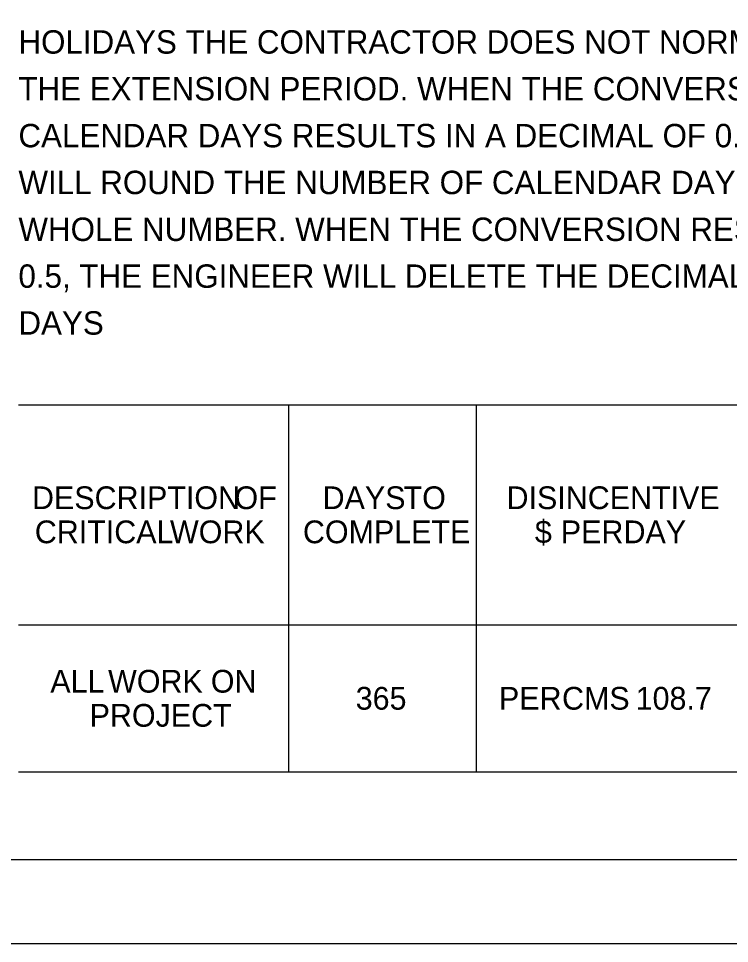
# Model space of a CAD drawing. Extents: x 0 to 84.3, y -13.4 to 22.
# Drawn here: x 24.66 to 28.91, y 0 to 5.53 of the extents above; entities that cross this region are included whole.
import ezdxf

# ---------------------------------------------------------------- set-up
doc = ezdxf.new("R2010")
doc.units = 0
for name, color, linetype in [('SH_Border', 7, 'Continuous'), ('SH_Cut_Line', 7, 'Continuous'), ('SH_Text', 7, 'Continuous')]:
    doc.layers.add(name, color=color, linetype=linetype)

msp = doc.modelspace()

# ---------------------------------------------------------------- linework, layer by layer
at = {"layer": 'SH_Border'}
msp.add_lwpolyline([(1.5, 21.5), (33.5, 21.5), (33.5, 0.5), (1.5, 0.5)], close=True, dxfattribs=at)
at = {"layer": 'SH_Cut_Line'}
msp.add_lwpolyline([(0, 0), (34, 0), (34, 22), (0, 22)], close=True, dxfattribs=at)
at = {"layer": 'SH_Text'}
for p, q in [((24.66, 3.22), (31.5436, 3.22)), ((26.2754, 1.0259), (26.2754, 3.22)), ((27.3966, 1.0259), (27.3966, 3.22)), ((24.66, 1.906), (31.5436, 1.906)), ((24.66, 1.0259), (31.5436, 1.0259))]:
    msp.add_line(p, q, dxfattribs=at)

# ---------------------------------------------------------------- texts
for s, height, p in [('HOLIDAYS THE CONTRACTOR DOES NOT NORMALLY WORK THAT OCCUR IN ', 0.14, (24.66, 5.32)), ('THE EXTENSION PERIOD. WHEN THE CONVERSION OF WORKDAYS TO ', 0.14, (24.66, 5.04)), ('CALENDAR DAYS RESULTS IN A DECIMAL OF 0.5 OR GREATER, THE ENGINEER ', 0.14, (24.66, 4.76)), ('WILL ROUND THE NUMBER OF CALENDAR DAYS TO THE NEXT HIGHEST ', 0.14, (24.66, 4.48)), ('WHOLE NUMBER. WHEN THE CONVERSION RESULTS IN A DECIMAL LESS THAN ', 0.14, (24.66, 4.2)), ('0.5, THE ENGINEER WILL DELETE THE DECIMAL PORTION OF THE CALENDAR ', 0.14, (24.66, 3.92)), ('DAYS', 0.14, (24.66, 3.64)), ('DESCRIPTION', 0.13601, (24.7411, 2.597)), (' OF', 0.13601, (25.9005, 2.597)), ('DAYS', 0.13601, (26.4778, 2.597)), (' TO', 0.13601, (26.9111, 2.597)), ('DISINCENTIVE', 0.13601, (27.577, 2.597)), ('CRITICAL', 0.13601, (24.7578, 2.393)), (' WORK', 0.13601, (25.5151, 2.393)), ('COMPLETE', 0.13601, (26.3601, 2.393)), ('$', 0.136, (27.7463, 2.393)), (' PER', 0.13601, (27.8507, 2.393)), (' DAY', 0.13601, (28.2255, 2.393)), ('ALL', 0.13601, (24.8506, 1.4999)), (' WORK', 0.13601, (25.1451, 1.4999)), (' ON', 0.13601, (25.7592, 1.4999)), ('365', 0.13601, (26.6755, 1.3979)), ('PER', 0.13601, (27.5315, 1.3979)), (' CMS', 0.13601, (27.8579, 1.3979)), (' 108.7', 0.13601, (28.2979, 1.3979)), ('PROJECT', 0.13601, (25.0855, 1.2959))]:
    msp.add_text(s, height=height, dxfattribs=at).set_placement(p)

doc.saveas('drawing.dxf')
